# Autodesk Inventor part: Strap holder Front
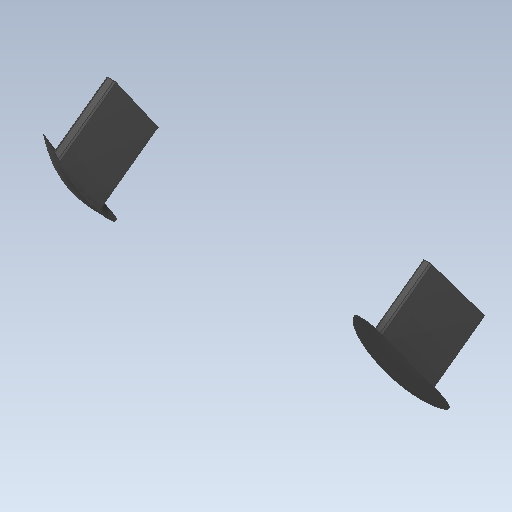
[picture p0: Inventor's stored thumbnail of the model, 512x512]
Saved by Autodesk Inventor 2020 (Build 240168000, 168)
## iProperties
Created: 2021-10
Part Number: Strap holder Front
Material: Steel
Document SubType Name: Modeling
Designer: bruno
Density: 7.85 g/cm^3
Appearance: Par défaut
Author: bruno
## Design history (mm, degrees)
feature "Body1"
feature "Body2"
node "Solide1"
node "Solide2"
